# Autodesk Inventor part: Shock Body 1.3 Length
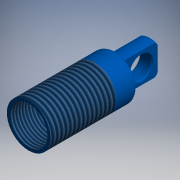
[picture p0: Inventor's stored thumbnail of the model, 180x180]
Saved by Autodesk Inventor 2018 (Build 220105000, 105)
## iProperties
Shininess: 28.0
Compacted: True
Length Units: 11272
Angle Units: 11279
Time Units: 11290
Mass Units: 11286
Length Display Precision: 4
Angle Display Precision: 2
Company: Autodesk
Created: 2000-03
Part Number: Shock Body 1.3 Length
Project: Inventor Samples
User Status: IN PROGRESS
Document SubType Name: Modeling
Designer: Autodesk, Inc.
Density: 1.13 g/cm^3
Mass: 1.29919 g
Surface Area: 23.4314 cm^2
Volume: 1.14973 cm^3
Material: Nylon-6/6
Appearance: Electric Blue
Density: 0.0
Volumn: 0.0
Area: 0.0
PropertySet Name: Model Information
Control State: 0
Master: False
Checked Out: False
Title: Shock Body 1.625 Length
Author: Autodesk, Inc.
Revision Number: A
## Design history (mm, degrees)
node "Extrusion1" dims "d1" = 25.4, "d2" = 0
  sketch "Sketch2"
    geometry: C1 r 6.35 at (-3.753, -1.332)
    constraints: 1 centre point
    dimensions: "d0" = 12.7 diameter of C1
workaxis "Work Axis1"
node "Shell1" dims "d17" = 0.889
node "Fillet2" dims "d18" = 1.27
node "Extrusion2" dims "d4" = 10.16, "d5" = 0
  sketch "Sketch3"
    geometry: C1 r 6.35 at (0, 0) reference; C2 r 4.763 at (0, 0)
    constraints: 1 centre point, 1 coincident
    dimensions: "d3" = 9.525 diameter of C2
node "Extrusion3" dims "d8" = 9.525, "d9" = 0
  sketch "Sketch4"
    geometry: L1 (-1.905, 4.365)-(-1.905, -4.365); L2 (1.905, 4.365)-(1.905, -4.365); A1 r 4.763 centre (0, 0) between (-1.905, 4.365) and (-1.905, -4.365) reference
    constraints: 4 end point, 4 point on circle, 1 parallel, 1 vertical
    dimensions: "d6" = 3.81 distance between parallel lines of L2 L1; "d7" = 1.905 distance from line of A1.centre L1 (= 0.5 x d6)
node "Extrusion4" dims "d13" = 9.525, "d14" = 0
  sketch "Sketch5"
    geometry: L1 (-9.525, 1.438)-(-9.525, 7.292) reference; L2 (-17.272, 4.365)-(32.512, 4.365) reference; C1 r 3.048 at (-5.397, 4.365)
    constraints: 1 centre point, 1 point on line
    dimensions: "d11" = 4.7625 distance from line of C1.centre L1; "d12" = 6.096 diameter of C1
node "Chamfer1" dims "d15" = 0.381, "d16" = 0.381, "d26" = 45 deg
node "Fillet3" dims "d19" = 1.27
thread "Thread1" dims "d20" = 19.05, "d21" = 0
thread "Thread2" dims "d22" = 9.525, "d23" = 0
sketch "Sketch6"
  geometry: C1 r 9.593 at (10.978, -0.3)
  constraints: 1 centre point
extrude "Extrusion5" cut sketch "Sketch6" stored distance "d24" = 25.4; taper "d25" = 0 deg
workplane "Work Plane1"
body "Solid1"
